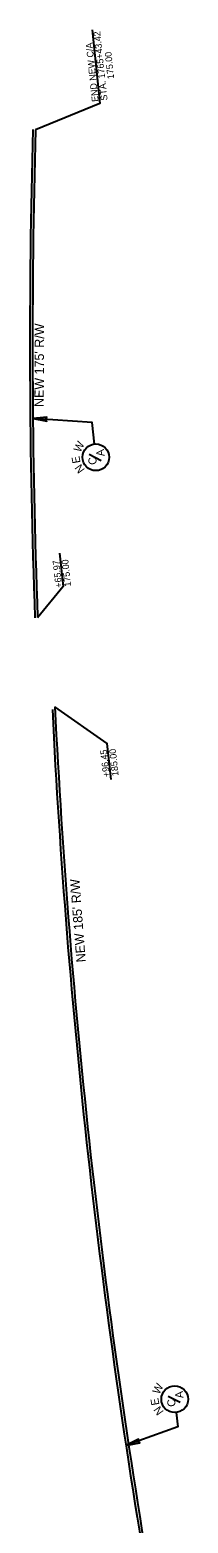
# Model space of a CAD drawing. Extents: x 2003184 to 2010449, y 855784 to 861212.
# Drawn here: x 2004430 to 2004548, y 860092 to 861212 of the extents above; entities that cross this region are included whole.
import ezdxf

# ---------------------------------------------------------------- set-up
doc = ezdxf.new("R2010")
doc.units = 0
for name, color, linetype in [('RD_PD_Control_Access', 7, 'Continuous'), ('RD_PD_RW', 7, 'Continuous'), ('RD_PD_RW_TX', 7, 'Continuous')]:
    doc.layers.add(name, color=color, linetype=linetype)

msp = doc.modelspace()

# ---------------------------------------------------------------- linework, layer by layer
at = {"layer": 'RD_PD_Control_Access'}
for p, q in [((2004474.3, 860893.8), (2004483.3, 860889.1)), ((2004533.5, 860187.5), (2004542.4, 860182.8))]:
    msp.add_line(p, q, dxfattribs=at)
for points in [[(2004476.5, 861211.9), (2004482.4, 861156.7), (2004434.2, 861137)], [(2004478.3, 860901.3), (2004476.5, 860917.5), (2004432.3, 860920.6)], [(2004539.5, 860175.1), (2004540.7, 860164.4), (2004501.9, 860150.3)]]:
    msp.add_lwpolyline(points, dxfattribs=at)
for points in [[(2004432.3, 860920.6), (2004442.5, 860918.4), (2004441, 860920), (2004442.7, 860921.4)], [(2004501.9, 860150.3), (2004512.2, 860152.4), (2004510.2, 860153.3), (2004511.2, 860155.2)]]:
    msp.add_lwpolyline(points, close=True, dxfattribs=at)
for centre in [(2004479.3, 860891.4), (2004538.4, 860185.1)]:
    msp.add_circle(centre, 10, dxfattribs=at)
for radius, start, end in [(5556.6, 178.3534, 182.1279), (5546.6, 182.8439, 189.7888)]:
    msp.add_arc((2009986.5, 860977.4), radius, start, end, dxfattribs=at)
at = {"layer": 'RD_PD_RW'}
for radius, start, end in [(5554.6, 178.3534, 182.1279), (5544.6, 182.8232, 189.7877)]:
    msp.add_arc((2009986.5, 860977.4), radius, start, end, dxfattribs=at)
at = {"layer": 'RD_PD_RW_TX'}
for points in [[(2004452.2, 860819.5), (2004454.9, 860794.6), (2004435.7, 860771.1)], [(2004490.8, 860649.9), (2004487.9, 860676.8), (2004448.6, 860704.3)]]:
    msp.add_lwpolyline(points, dxfattribs=at)

# ---------------------------------------------------------------- texts
at = {"layer": 'RD_PD_Control_Access'}
for s, height, rotation, p in [('STA. 1765+43.42', 5, 96.1251, (2004488.1, 861159.1)), ('END NEW C/A', 5, 96.1251, (2004481.4, 861158.2)), ('175.00', 5, 96.1251, (2004493.1, 861175.3)), ('W', 6, 62.6413, (2004467.6, 860894.6)), ('A', 6, 96.1251, (2004485.9, 860892.4)), ('E', 6, 100.3188, (2004467.9, 860887.4)), ('N', 6, 125.4371, (2004471.3, 860882.1)), ('C', 6, 96.1251, (2004480.1, 860886.1)), ('W', 6, 62.6413, (2004526.7, 860188.3)), ('A', 6, 96.1251, (2004545, 860186.1)), ('E', 6, 100.3188, (2004527, 860181.1)), ('C', 6, 96.1251, (2004539.2, 860179.8)), ('N', 6, 125.4371, (2004530.4, 860175.8))]:
    msp.add_text(s, height=height, rotation=rotation, dxfattribs=at).set_placement(p)
at = {"layer": 'RD_PD_RW_TX'}
for s, height, rotation, p in [("NEW 175' R/W", 7, 89.7541, (2004440.3, 860929.1)), ('+65.97', 5, 96.1251, (2004454.1, 860793.9)), ('175.00', 5, 96.1251, (2004460.8, 860794.7)), ('+96.45', 5, 96.1251, (2004489.7, 860651.9)), ('185.00', 5, 96.1251, (2004496.4, 860652.7)), ("NEW 185' R/W", 7, 94.4706, (2004471.8, 860513))]:
    msp.add_text(s, height=height, rotation=rotation, dxfattribs=at).set_placement(p)

doc.saveas('drawing.dxf')
